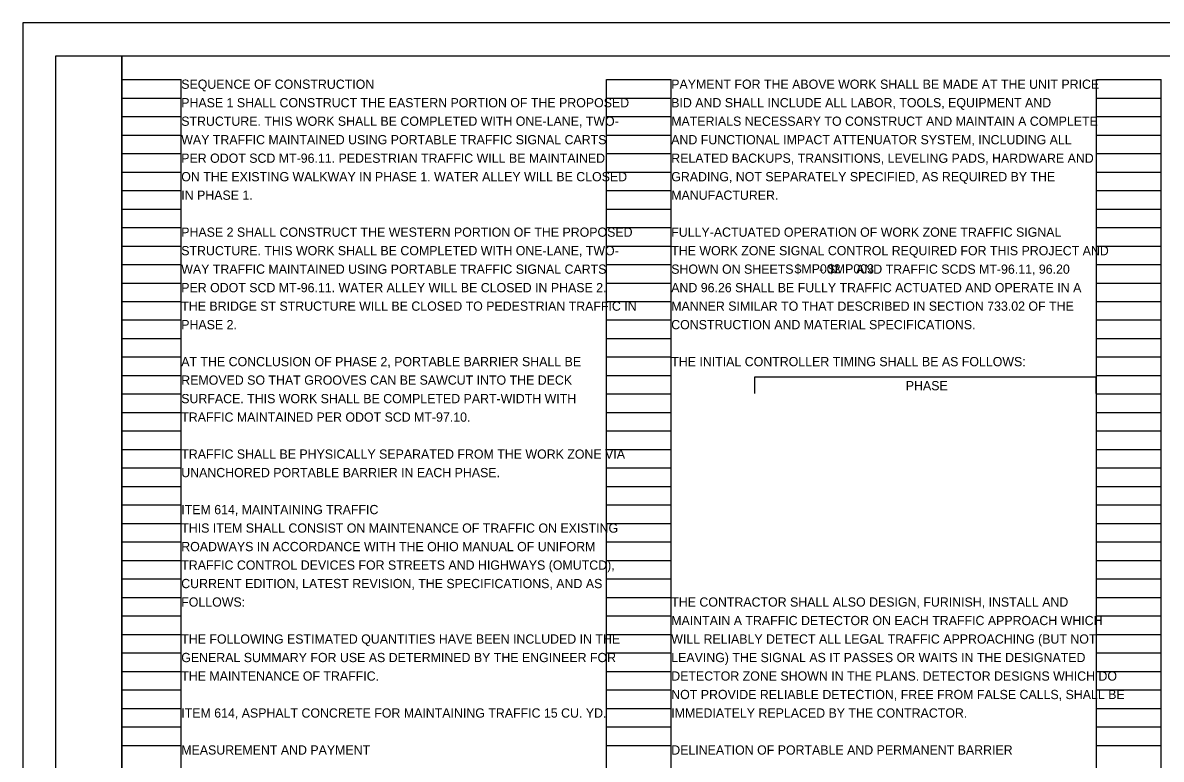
# Model space of a CAD drawing. Extents: x 0 to 34, y 0 to 22.
# Drawn here: x 0 to 17.24, y 10.85 to 22 of the extents above; entities that cross this region are included whole.
import ezdxf

# ---------------------------------------------------------------- set-up
doc = ezdxf.new("R2010")
doc.units = 0
for name, color, linetype in [('SH_Border', 7, 'Continuous'), ('SH_Cut_Line', 7, 'Continuous'), ('SH_Data', 7, 'Continuous'), ('SH_Text', 7, 'Continuous')]:
    doc.layers.add(name, color=color, linetype=linetype)

msp = doc.modelspace()

# ---------------------------------------------------------------- linework, layer by layer
at = {"layer": 'SH_Border'}
for points in [[(0.5, 21.5), (1.5, 21.5), (1.5, 0.5), (0.5, 0.5)], [(1.5, 21.5), (33.5, 21.5), (33.5, 0.5), (1.5, 0.5)]]:
    msp.add_lwpolyline(points, close=True, dxfattribs=at)
at = {"layer": 'SH_Cut_Line'}
msp.add_lwpolyline([(0, 0), (34, 0), (34, 22), (0, 22)], close=True, dxfattribs=at)
at = {"layer": 'SH_Data'}
for p, q in [((1.5, 0.98), (1.5, 21.14)), ((1.5, 21.14), (2.4, 21.14)), ((2.4, 0.98), (2.4, 21.14)), ((8.84, 0.98), (8.84, 21.14)), ((8.84, 21.14), (9.82, 21.14)), ((9.82, 0.98), (9.82, 21.14)), ((16.26, 0.98), (16.26, 21.14)), ((16.26, 21.14), (17.24, 21.14)), ((17.24, 0.98), (17.24, 21.14)), ((1.5, 20.86), (2.4, 20.86)), ((8.84, 20.86), (9.82, 20.86)), ((16.26, 20.86), (17.24, 20.86)), ((1.5, 20.58), (2.4, 20.58)), ((8.84, 20.58), (9.82, 20.58)), ((16.26, 20.58), (17.24, 20.58)), ((1.5, 20.3), (2.4, 20.3)), ((8.84, 20.3), (9.82, 20.3)), ((16.26, 20.3), (17.24, 20.3)), ((1.5, 20.02), (2.4, 20.02)), ((8.84, 20.02), (9.82, 20.02)), ((16.26, 20.02), (17.24, 20.02)), ((1.5, 19.74), (2.4, 19.74)), ((8.84, 19.74), (9.82, 19.74)), ((16.26, 19.74), (17.24, 19.74)), ((1.5, 19.46), (2.4, 19.46)), ((8.84, 19.46), (9.82, 19.46)), ((16.26, 19.46), (17.24, 19.46)), ((1.5, 19.18), (2.4, 19.18)), ((8.84, 19.18), (9.82, 19.18)), ((16.26, 19.18), (17.24, 19.18)), ((1.5, 18.9), (2.4, 18.9)), ((8.84, 18.9), (9.82, 18.9)), ((16.26, 18.9), (17.24, 18.9)), ((1.5, 18.62), (2.4, 18.62)), ((8.84, 18.62), (9.82, 18.62)), ((16.26, 18.62), (17.24, 18.62)), ((1.5, 18.34), (2.4, 18.34)), ((8.84, 18.34), (9.82, 18.34)), ((16.26, 18.34), (17.24, 18.34)), ((1.5, 18.06), (2.4, 18.06)), ((8.84, 18.06), (9.82, 18.06)), ((16.26, 18.06), (17.24, 18.06)), ((1.5, 17.78), (2.4, 17.78)), ((8.84, 17.78), (9.82, 17.78)), ((16.26, 17.78), (17.24, 17.78)), ((1.5, 17.5), (2.4, 17.5)), ((8.84, 17.5), (9.82, 17.5)), ((16.26, 17.5), (17.24, 17.5)), ((1.5, 17.22), (2.4, 17.22)), ((8.84, 17.22), (9.82, 17.22)), ((16.26, 17.22), (17.24, 17.22)), ((1.5, 16.94), (2.4, 16.94)), ((8.84, 16.94), (9.82, 16.94)), ((16.26, 16.94), (17.24, 16.94)), ((1.5, 16.66), (2.4, 16.66)), ((8.84, 16.66), (9.82, 16.66)), ((16.26, 16.66), (17.24, 16.66)), ((1.5, 16.38), (2.4, 16.38)), ((8.84, 16.38), (9.82, 16.38)), ((16.26, 16.38), (17.24, 16.38)), ((1.5, 16.1), (2.4, 16.1)), ((8.84, 16.1), (9.82, 16.1)), ((16.26, 16.1), (17.24, 16.1)), ((1.5, 15.82), (2.4, 15.82)), ((8.84, 15.82), (9.82, 15.82)), ((16.26, 15.82), (17.24, 15.82)), ((1.5, 15.54), (2.4, 15.54)), ((8.84, 15.54), (9.82, 15.54)), ((16.26, 15.54), (17.24, 15.54)), ((1.5, 15.26), (2.4, 15.26)), ((8.84, 15.26), (9.82, 15.26)), ((16.26, 15.26), (17.24, 15.26)), ((1.5, 14.98), (2.4, 14.98)), ((8.84, 14.98), (9.82, 14.98)), ((16.26, 14.98), (17.24, 14.98)), ((1.5, 14.7), (2.4, 14.7)), ((8.84, 14.7), (9.82, 14.7)), ((16.26, 14.7), (17.24, 14.7)), ((1.5, 14.42), (2.4, 14.42)), ((8.84, 14.42), (9.82, 14.42)), ((16.26, 14.42), (17.24, 14.42)), ((1.5, 14.14), (2.4, 14.14)), ((8.84, 14.14), (9.82, 14.14)), ((16.26, 14.14), (17.24, 14.14)), ((1.5, 13.86), (2.4, 13.86)), ((8.84, 13.86), (9.82, 13.86)), ((16.26, 13.86), (17.24, 13.86)), ((1.5, 13.58), (2.4, 13.58)), ((8.84, 13.58), (9.82, 13.58)), ((16.26, 13.58), (17.24, 13.58)), ((1.5, 13.3), (2.4, 13.3)), ((8.84, 13.3), (9.82, 13.3)), ((16.26, 13.3), (17.24, 13.3)), ((1.5, 13.02), (2.4, 13.02)), ((8.84, 13.02), (9.82, 13.02)), ((16.26, 13.02), (17.24, 13.02)), ((1.5, 12.74), (2.4, 12.74)), ((8.84, 12.74), (9.82, 12.74)), ((16.26, 12.74), (17.24, 12.74)), ((1.5, 12.46), (2.4, 12.46)), ((8.84, 12.46), (9.82, 12.46)), ((16.26, 12.46), (17.24, 12.46)), ((1.5, 12.18), (2.4, 12.18)), ((8.84, 12.18), (9.82, 12.18)), ((16.26, 12.18), (17.24, 12.18)), ((1.5, 11.9), (2.4, 11.9)), ((8.84, 11.9), (9.82, 11.9)), ((16.26, 11.9), (17.24, 11.9)), ((1.5, 11.62), (2.4, 11.62)), ((8.84, 11.62), (9.82, 11.62)), ((16.26, 11.62), (17.24, 11.62)), ((1.5, 11.34), (2.4, 11.34)), ((8.84, 11.34), (9.82, 11.34)), ((16.26, 11.34), (17.24, 11.34)), ((1.5, 11.06), (2.4, 11.06)), ((8.84, 11.06), (9.82, 11.06)), ((16.26, 11.06), (17.24, 11.06))]:
    msp.add_line(p, q, dxfattribs=at)
at = {"layer": 'SH_Text'}
msp.add_lwpolyline([(11.086, 16.389), (11.086, 16.639), (16.248, 16.639), (16.248, 16.389)], dxfattribs=at)

# ---------------------------------------------------------------- texts
for s, p in [('SEQUENCE OF CONSTRUCTION', (2.4, 21)), ('PAYMENT FOR THE ABOVE WORK SHALL BE MADE AT THE UNIT PRICE ', (9.82, 21)), ('PHASE 1 SHALL CONSTRUCT THE EASTERN PORTION OF THE PROPOSED ', (2.4, 20.72)), ('BID AND SHALL INCLUDE ALL LABOR, TOOLS, EQUIPMENT AND ', (9.82, 20.72)), ('STRUCTURE. THIS WORK SHALL BE COMPLETED WITH ONE-LANE, TWO-', (2.4, 20.44)), ('MATERIALS NECESSARY TO CONSTRUCT AND MAINTAIN A COMPLETE ', (9.82, 20.44)), ('WAY TRAFFIC MAINTAINED USING PORTABLE TRAFFIC SIGNAL CARTS ', (2.4, 20.16)), ('AND FUNCTIONAL IMPACT ATTENUATOR SYSTEM, INCLUDING ALL ', (9.82, 20.16)), ('PER ODOT SCD MT-96.11. PEDESTRIAN TRAFFIC WILL BE MAINTAINED ', (2.4, 19.88)), ('RELATED BACKUPS, TRANSITIONS, LEVELING PADS, HARDWARE AND ', (9.82, 19.88)), ('ON THE EXISTING WALKWAY IN PHASE 1. WATER ALLEY WILL BE CLOSED ', (2.4, 19.6)), ('GRADING, NOT SEPARATELY SPECIFIED, AS REQUIRED BY THE ', (9.82, 19.6)), ('IN PHASE 1. ', (2.4, 19.32)), ('MANUFACTURER.', (9.82, 19.32)), ('PHASE 2 SHALL CONSTRUCT THE WESTERN PORTION OF THE PROPOSED ', (2.4, 18.76)), ('FULLY-ACTUATED OPERATION OF WORK ZONE TRAFFIC SIGNAL', (9.82, 18.76)), ('STRUCTURE. THIS WORK SHALL BE COMPLETED WITH ONE-LANE, TWO-', (2.4, 18.48)), ('THE WORK ZONE SIGNAL CONTROL REQUIRED FOR THIS PROJECT AND ', (9.82, 18.48)), ('WAY TRAFFIC MAINTAINED USING PORTABLE TRAFFIC SIGNAL CARTS ', (2.4, 18.2)), ('SHOWN ON SHEETS', (9.82, 18.2)), ('AND TRAFFIC SCDS MT-96.11, 96.20 ', (12.62, 18.2)), ('-', (12.06, 18.2)), ('PER ODOT SCD MT-96.11. WATER ALLEY WILL BE CLOSED IN PHASE 2. ', (2.4, 17.92)), ('AND 96.26 SHALL BE FULLY TRAFFIC ACTUATED AND OPERATE IN A ', (9.82, 17.92)), ('THE BRIDGE ST STRUCTURE WILL BE CLOSED TO PEDESTRIAN TRAFFIC IN ', (2.4, 17.64)), ('MANNER SIMILAR TO THAT DESCRIBED IN SECTION 733.02 OF THE ', (9.82, 17.64)), ('PHASE 2. ', (2.4, 17.36)), ('CONSTRUCTION AND MATERIAL SPECIFICATIONS. ', (9.82, 17.36)), ('AT THE CONCLUSION OF PHASE 2, PORTABLE BARRIER SHALL BE ', (2.4, 16.8)), ('THE INITIAL CONTROLLER TIMING SHALL BE AS FOLLOWS:', (9.82, 16.8)), ('REMOVED SO THAT GROOVES CAN BE SAWCUT INTO THE DECK ', (2.4, 16.52)), ('SURFACE. THIS WORK SHALL BE COMPLETED PART-WIDTH WITH ', (2.4, 16.24)), ('TRAFFIC MAINTAINED PER ODOT SCD MT-97.10.', (2.4, 15.96)), ('TRAFFIC SHALL BE PHYSICALLY SEPARATED FROM THE WORK ZONE VIA ', (2.4, 15.4)), ('UNANCHORED PORTABLE BARRIER IN EACH PHASE. ', (2.4, 15.12)), ('ITEM 614, MAINTAINING TRAFFIC', (2.4, 14.56)), ('THIS ITEM SHALL CONSIST ON MAINTENANCE OF TRAFFIC ON EXISTING ', (2.4, 14.28)), ('ROADWAYS IN ACCORDANCE WITH THE OHIO MANUAL OF UNIFORM ', (2.4, 14)), ('TRAFFIC CONTROL DEVICES FOR STREETS AND HIGHWAYS (OMUTCD), ', (2.4, 13.72)), ('CURRENT EDITION, LATEST REVISION, THE SPECIFICATIONS, AND AS ', (2.4, 13.44)), ('FOLLOWS:', (2.4, 13.16)), ('THE CONTRACTOR SHALL ALSO DESIGN, FURINISH, INSTALL AND ', (9.82, 13.16)), ('MAINTAIN A TRAFFIC DETECTOR ON EACH TRAFFIC APPROACH WHICH ', (9.82, 12.88)), ('THE FOLLOWING ESTIMATED QUANTITIES HAVE BEEN INCLUDED IN THE ', (2.4, 12.6)), ('WILL RELIABLY DETECT ALL LEGAL TRAFFIC APPROACHING (BUT NOT ', (9.82, 12.6)), ('GENERAL SUMMARY FOR USE AS DETERMINED BY THE ENGINEER FOR ', (2.4, 12.32)), ('LEAVING) THE SIGNAL AS IT PASSES OR WAITS IN THE DESIGNATED ', (9.82, 12.32)), ('THE MAINTENANCE OF TRAFFIC.', (2.4, 12.04)), ('DETECTOR ZONE SHOWN IN THE PLANS. DETECTOR DESIGNS WHICH DO ', (9.82, 12.04)), ('NOT PROVIDE RELIABLE DETECTION, FREE FROM FALSE CALLS, SHALL BE ', (9.82, 11.76)), ('ITEM 614, ASPHALT CONCRETE FOR MAINTAINING TRAFFIC 15 CU. YD. ', (2.4, 11.48)), ('IMMEDIATELY REPLACED BY THE CONTRACTOR. ', (9.82, 11.48)), ('MEASUREMENT AND PAYMENT', (2.4, 10.92)), ('DELINEATION OF PORTABLE AND PERMANENT BARRIER', (9.82, 10.92))]:
    msp.add_text(s, height=0.14, rotation=360, dxfattribs=at).set_placement(p)
for s, p in [('$MP002', (11.687, 18.204)), ('$MP003', (12.193, 18.204)), ('PHASE', (13.372, 16.436))]:
    msp.add_text(s, height=0.14, dxfattribs=at).set_placement(p)

doc.saveas('drawing.dxf')
